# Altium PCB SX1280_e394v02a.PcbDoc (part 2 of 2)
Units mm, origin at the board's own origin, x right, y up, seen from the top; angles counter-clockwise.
Board outline 104.5 x 58 mm, 4 copper layers (Top Layer, MidLayer1, MidLayer2, Bottom Layer), stack 0.995 mm thick; 155 components, 106 nets, 471 pads, 1470 vias.
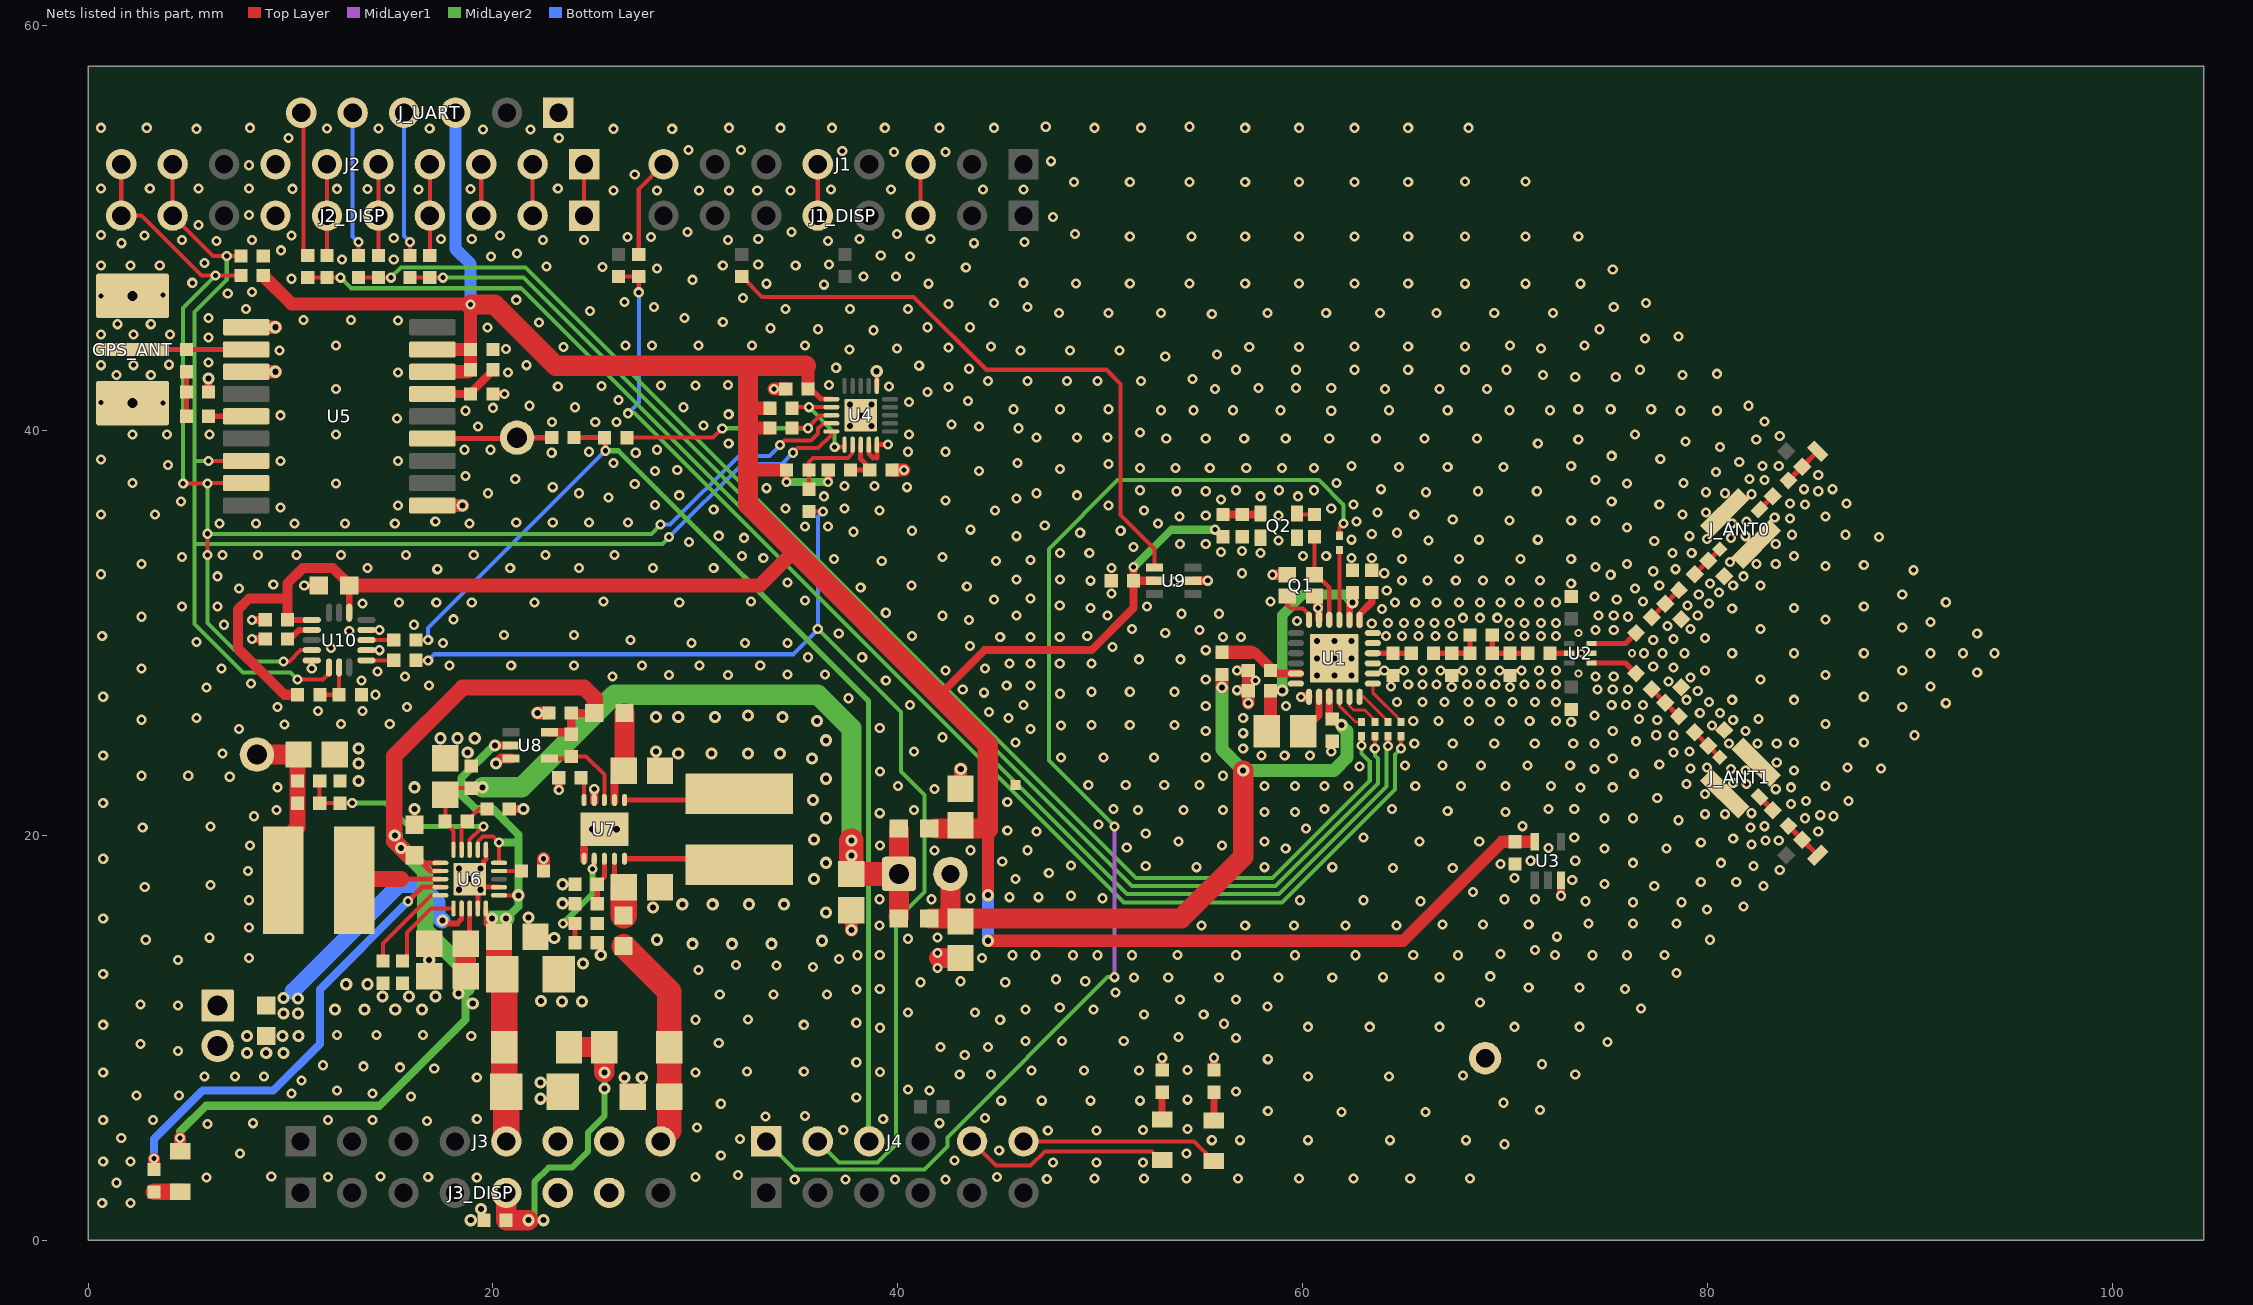
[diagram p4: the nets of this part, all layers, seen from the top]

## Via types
v1: diameter 0.5, hole 0.25, Top Layer to Bottom Layer, tented both sides, 1338 vias
v2: diameter 0.6, hole 0.3, Top Layer to Bottom Layer, tented both sides, 107 vias
v3: diameter 0.5, hole 0.3, Top Layer to Bottom Layer, tented top, 10 vias
v4: diameter 0.6, hole 0.3, Top Layer to Bottom Layer, tented top, 9 vias
v5: diameter 0.4, hole 0.2, Top Layer to Bottom Layer, tented both sides, 4 vias
v6: diameter 0.66, hole 0.33, Top Layer to Bottom Layer, tented top, 2 vias

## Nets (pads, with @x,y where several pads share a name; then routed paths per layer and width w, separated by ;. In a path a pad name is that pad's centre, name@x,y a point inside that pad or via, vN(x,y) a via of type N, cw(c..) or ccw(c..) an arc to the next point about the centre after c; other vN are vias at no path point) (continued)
GND: BAT1.2 C0.2 C1.1 C2.1 C5.1 C6.1 C7.1 C8.1 C9.1 C10.1 C11.1 C12.1 C13.1 C16.2 C17.2 C20.2 C21.1 C22.1 C23.1 C24.2 C25.2 C26.1 C27.1 C28.1 C29.1 C30.1 C31.2 C33.1 C34.1 C35.1 C36.1 C37.1 C38.1 C39.1 C40.1 C41.1 C42.2 C43.1 C44.1 C45.1 C46.1 C48.2 GND.1 GPS_ANT.2 J2.7 J2_DISP.7 J3.6 J3.7 J3_DISP.6 J3_DISP.7 J_ANT0.3 J_ANT0.4 J_ANT1.3 J_ANT1.4 J_UART.1 L5.1 L6.1 Q1.2 Q1.4 Q2.1 Q2.2 R14.1 R17.1 R18.1 R24.2 R25.2 R27.2 R29.2 R31.2 R32.2 R34.1 R37.1 R45.2 Shield.1 U1.5 U1.13 U1.20 U1.21 U1.23 U1.24 U1.25 U2.2 U3.3 U4.6 U4.19 U4.20 U4.21 U5.1 U5.10 U5.12 U6.2 U6.6 U6.19 U6.21 U7.4 U7.6 U7.11 U8.3 U9.2 U10.5 U10.10 U10.12 | length 33.6
  Top Layer w0.25: v2(5.95,42.575) v2@5.957,42.568 ; C29.1@16.125,20.525 v2(16.125,21.3) ; U6.19@19.25,16.394 U6.21@19.25,17.444 ; U6.6@19.65,19.294 19.65,18.829 19.537,18.716 19.537,18.532 v3(19.375,18.369) v3(18.85,17.844) U6.21@19.25,17.444 ; U6.2@20.3,17.444 U6.21@19.25,17.444 ; U4.19@38.561,39.3 38.561,38.861 38.772,38.65 ; v2(38.95,42.925) 38.95,42.875 38.961,42.864 U4.6@38.961,42.2 ; 38.961,38.65 U4.20@38.961,39.3 v1(39.5,39.3)
  Top Layer w0.3: v1(11.05,28.25) U10.5@11.05,28.65 ; U10.10@13.75,29.15 v1(14.4,29.15) ; U10.12@13.75,30.15 v1(14.4,30.15)
  Top Layer w0.4: C42.2@5.957,41.95 v2@5.957,42.568 ; v1(8.1,29.7) C44.1@8.75,29.7 ; v1@8.1,30.664 8.114,30.65 C43.1@8.75,30.65 ; v1@10.679,32.35 C45.1@11.4,32.35 ; C24.2@19.995,41.8 v1(20.575,41.8) ; R27.2@20.8,21.3 v2(21.5,21.3) ; v1(23.25,22.25) R32.2@23.25,22.85 ; U7.6@24.5,18.794 U7.6@24.5,18.85 24.5,19.35 ; U7.4@25,21.65 U7.4@25,21.75 v1(25,22.284) ; R17.1@53.05,8.421 v1(53.05,9.021) ; U9.2@54.569,32.58 v1(55.3,32.581) ; R18.1@55.6,8.421 v1(55.6,9.021) ; Q1.2@60.575,31.825 Q1.2@60.75,31.65 ; v1(60.75,31.228) 60.8,31.178 U1.5@60.8,30.65 ; v1@72.75,17.022 U3.3@72.75,17.789
  Top Layer w0.5: v2(20.15,23.55) 20.396,23.796 U8.3@20.892,23.796 ; v1(56.75,28.15) C8.1@57.3,28.15 ; v1@56.774,27.174 57.276,27.174 C9.1@57.3,27.15 ; v1(58.5,32.875) Q1.4@59.225,32.875 ; v1(59.896,26.83) 60.205,26.83 U1.13@60.225,26.85 ; v1(60.75,31.228) Q1.2@60.75,31.65
  Top Layer w0.6: v1(57.3,26.532) C9.1@57.3,27.15 C8.1@57.3,28.15
  Top Layer w0.65: U5.12@7.81,42.9 v2(9.25,42.9) ; U5.10@7.81,45.1 v2(9.25,45.1) ; U5.1@17.01,36.3 v2(18.5,36.3) ; v2(22.2,26.05) C30.1@22.767,26.05 ; R25.2@22.5,18.244 v1(22.5,18.85) ; v1(33.875,42.05) C20.2@34.461,42.05 ; v2(37.7,15.325) C40.1@37.7,16.3 ; R14.1@39.711,38.05 v1(40.3,38.05) ; C13.1@43.09,22.3 43.09,23.265 v2(43.1,23.275)
  Top Layer w1: 42.04,13.95 C7.1@43.09,13.95
  other v1: 0.7,1.85 2.1,1.85 1.4,2.85 34.9,3 37.4,3 39.85,3 42.35,3 47.35,3.037 49.7,3.05 52.15,3.05 54.25,3.05 56.8,3.05 59.8,3.05 62.5,3.05 65.3,3.05 68.25,3.05 5.85,3.1 19.2,3.1 11.85,3.13 16.8,3.13 30,3.13 44.9,3.13 14.45,3.15 9.05,3.166 32.1,3.237 47.65,3.85 49.8,3.85 52.1,3.85 0.75,3.9 2.1,3.9 42.8,3.95 31.25,4.2 7.5,4.3 54.25,4.3 45,4.45 69.95,4.75 55.5,4.95 56.886,4.95 60.25,4.95 64.3,4.95 68.05,4.95 32.2,5 1.64,5.05 47.4,5.435 49.8,5.435 37.3,5.45 52.1,5.45 54.3,5.5 30.067,5.578 5.9,5.75 8.15,5.79 42.05,5.79 16.75,5.9 0.75,5.95 3.2,5.95 11.85,5.95 14.05,5.95 19.2,6 39.271,6 44.3,6.05 33.45,6.125 35.4,6.15 61.9,6.35 66.05,6.35 58.264,6.4 71.7,6.45 31.25,6.75 69.9,6.8 45.1,6.9 47.1,6.9 49.5,6.9 51.95,6.9 54.3,6.95 37.943,7.05 15.95,7.1 2.4,7.15 4.5,7.15 10.05,7.25 14.05,7.25 56.7,7.35 12.3,7.4 41.55,7.4 40.49,7.45 10.55,7.9 19.2,8.05 5.75,8.1 7.25,8.1 8.7,8.1 60.25,8.1 64.25,8.1 67.9,8.15 43.05,8.2 44.6,8.2 73.45,8.2 0.75,8.3 30,8.3 39.11,8.321 32.55,8.35 35.35,8.35 46.6,8.4 49.192,8.4 51.9,8.4 54.3,8.421 17.1,8.5 15.4,8.55 13.6,8.6 11.6,8.65 71.8,8.7 37.943,8.8 58.264,8.95 43.3,9.15 4.45,9.35 42.1,9.55 44.44,9.55 2.6,9.7 31.15,9.75 75.05,9.8 46.3,9.85 48.1,9.85 51.15,9.85 56.7,10 53.85,10.05 18.925,10.1 12.3,10.15 14.25,10.15 16.55,10.15 39.11,10.504 60.25,10.55 63.3,10.55 66.75,10.55 70.45,10.55 73.65,10.55 0.75,10.65 35.35,10.65 56.1,10.7 37.943,10.75 30,10.9 45.05,10.9 32.6,10.906 52.15,11.15 55.1,11.15 40.49,11.25 43.8,11.264 46.3,11.4 49.65,11.4 76.7,11.45 47.991,11.5 58.249,11.55 4.45,11.6 2.6,11.65 68.75,11.75 53.931,11.9 56.7,11.9 31.2,12.15 33.85,12.15 36.5,12.15 50.75,12.25 37.95,12.4 39.1,12.425 75.9,12.425 71.15,12.5 73.65,12.5 41.12,12.75 45.299,12.75 43.081,12.8 49.25,12.8 47.8,12.9 51.65,12.977 53.35,12.977 55.85,12.977 58.8,12.977 61.45,12.977 63.95,13 66.75,13 69.25,13.044 0.75,13.15 78.45,13.2 30.15,13.35 41.947,13.45 35.8,13.5 34,13.585 32,13.6 4.45,13.85 37.083,13.9 7.95,13.95 44.159,13.95 37.998,14.085 39.1,14.1 45.65,14.085 46.8,14.085 48.65,14.085 49.85,14.085 51.564,14.085 53.8,14.1 56.7,14.085 59.6,14.085 62.6,14.085 65.45,14.1 67.65,14.085 72.45,14.1 74.3,14.085 76,14.085 77.85,14.1 69.75,14.15 41.947,14.2 71.462,14.35 2.85,14.85 80.1,14.85 40.49,14.9 6,14.95 41.947,14.967 72.55,15 7.95,15.45 39.084,15.55 55,15.55 57.15,15.55 59.55,15.55 62.1,15.55 64.616,15.55 66.9,15.6 68.9,15.6 71.15,15.6 74.1,15.65 76.3,15.65 78.45,15.65 0.75,15.9 79.95,16.35 81.75,16.5 76.3,16.7 78.7,16.7 65.8,16.75 73.95,16.75 7.95,16.8 59.85,16.8 63,16.8 39.084,16.85 41.65,16.85 69.95,16.85 71.462,16.85 43.587,16.9 50.1,16.9 45.5,16.95 46.95,16.95 48.55,17.022 72.751,17.022 68.4,17.2 2.8,17.45 77.35,17.5 82.75,17.5 6.05,17.55 74.9,17.6 79.65,17.7 81.4,17.7 73.3,17.8 45.8,17.85 70.45,17.9 47.45,18.15 7.9,18.25 83.55,18.3 64.45,18.4 67.4,18.4 54.75,18.433 58.1,18.433 61.45,18.433 48.55,18.523 52.239,18.5 82.25,18.5 69.766,18.592 76.3,18.65 80.65,18.65 45.15,18.709 71.25,18.75 73.45,18.75 0.75,18.85 41.8,19.25 43.587,19.268 46.4,19.268 59.15,19.35 74.9,19.35 77.95,19.35 72.124,19.386 51.3,19.4 8,19.5 39.11,19.5 56,19.5 82.15,19.55 79.65,19.65 53.85,19.7 58.1,19.7 65.75,19.7 68.707,19.7 82.85,19.75 83.5,19.75 81.25,19.85 63,19.9 73.4,19.9 52.239,20.1 46.85,20.2 85.45,20.2 45.4,20.25 60.149,20.35 2.7,20.4 82.1,20.4 6.05,20.45 70.85,20.457 82.8,20.457 49.9,20.55 78.55,20.75 74.9,20.85 76.3,20.85 84.8,20.85 8.2,20.95 86.2,20.95 85.55,21 79.85,21.05 80.85,21.05 39.1,21.1 82.15,21.1 58.1,21.15 59.6,21.15 70,21.15 67.15,21.2 9.3,21.25 40.8,21.25 51.85,21.25 54.1,21.25 56.05,21.25 50.65,21.3 61.057,21.3 64.4,21.3 72.124,21.3 73.4,21.3 84.1,21.55 0.75,21.6 45.4,21.65 84.85,21.7 86.95,21.7 77.5,21.85 79.85,22.05 41.8,22.3 83.35,22.284 9.35,22.378 73.7,22.36 75.3,22.378 84.1,22.378 40,22.45 58.1,22.45 59.6,22.45 61.057,22.45 62.25,22.45 65.55,22.45 67.8,22.45 70,22.45 72.25,22.45 85.8,22.45 49.4,22.5 51.25,22.5 53.15,22.5 54.9,22.5 78.95,22.55 81.9,22.55 81.25,22.6 7,22.9 2.65,22.95 4.95,22.95 56.05,22.95 76.35,23.05 39.11,23.15 81.85,23.2 84.25,23.2 74.4,23.275 81.15,23.275 79.15,23.3 88.55,23.3 79.95,23.35 86.9,23.35 62.8,23.4 65.05,23.45 66.9,23.45 68.8,23.45 71.1,23.45 73.2,23.45 77.6,23.5 83.4,23.6 75.3,23.8 48.05,23.85 50.15,23.85 52.65,23.85 55.2,23.85 0.75,23.95 57.95,23.95 59.1,23.95 60.35,23.95 6.65,24.05 78.3,24.1 40.8,24.15 61.4,24.15 79.1,24.15 57.05,24.3 65.5,24.55 67.4,24.55 69.45,24.55 71.45,24.55 73.35,24.55 74.4,24.55 81.05,24.55 82.45,24.55 83.4,24.55 45.8,24.6 84.25,24.6 87.7,24.6 76.45,24.65 42.2,24.85 77.45,24.95 78.3,24.95 90.2,24.95 57.05,25.05 55.2,25.15 75.3,25.15 81.85,25.15 7.45,25.25 46.55,25.25 39.1,25.3 48.05,25.425 80.2,25.425 49.55,25.45 51.45,25.45 53.65,25.45 9.7,25.487 12.5,25.5 14.9,25.5 85.8,25.5 73.25,25.6 65.45,25.65 66.7,25.65 68.2,25.65 69.7,25.65 71.2,25.65 72.5,25.65 77.5,25.7 81.25,25.7 2.65,25.716 76.6,25.75 82.5,25.75 5.35,25.8 45.454,25.8 57.05,25.8 74.4,25.917 79.6,26.05 80.6,26.05 44.5,26.1 11.35,26.156 13.55,26.15 9.35,26.35 15.75,26.35 89.6,26.35 55.2,26.4 59.168,26.4 40.6,26.44 75.25,26.44 46.2,26.45 75.95,26.45 76.8,26.45 91.75,26.532 64.65,26.583 65.9,26.583 67,26.583 68.17,26.583 69.25,26.583 70.35,26.583 71.462,26.583 72.5,26.583 80.05,26.6 78.95,26.7 81.2,26.7 84.25,26.7 37.55,26.775 0.75,26.85 87.7,26.85 14.2,26.95 48,27 44.25,27.05 49.55,27.097 51.45,27.097 53.65,27.097 79.5,27.134 56.75,27.174 43.2,27.2 74.55,27.2 75.3,27.2 76.05,27.2 5.85,27.3 67.35,27.325 70.228,27.325 64.35,27.35 91,27.35 16.832,27.4 45.37,27.4 46.55,27.4 65.2,27.45 65.9,27.45 66.6,27.45 68.1,27.45 68.8,27.45 69.5,27.45 70.95,27.45 71.75,27.45 72.5,27.45 8.05,27.5 78.05,27.6 13.5,27.65 39.4,27.659 57.65,27.65 55.2,27.7 82.6,27.7 79.15,27.8 15.65,27.85 25.9,27.85 74.45,27.85 75.35,27.85 28.7,27.925 31.6,27.925 85.8,27.925 34.55,27.95 36.4,27.95 93.3,28.05 14.3,28.1 42.35,28.15 64.017,28.15 65,28.15 65.9,28.15 66.8,28.15 67.9,28.15 68.8,28.15 69.7,28.15 70.8,28.15 71.65,28.15 72.5,28.15 79.85,28.15 89.6,28.15 2.65,28.25 44.3,28.25 6.6,28.253 78.3,28.3 77.3,28.35 17.85,28.4 20.9,28.4 24,28.4 27.35,28.4 30.2,28.4 33.2,28.4 45.5,28.5 46.55,28.5 47.991,28.5 49.557,28.5 51.9,28.7 53.95,28.7 35.55,28.8 38.234,28.8 76.85,29 77.75,29 78.85,29 81.2,29 84.25,29 87.7,29 91,29 92.6,29 94.15,29 55.2,29.15 12,29.25 50.59,29.3 43.55,29.35 17.533,29.5 29.8,29.5 32.45,29.5 34.55,29.5 5.35,29.55 26.8,29.65 77.3,29.65 78.3,29.7 79.85,29.75 45.05,29.8 46.55,29.8 47.991,29.8 56.05,29.8 56.95,29.8 0.7,29.85 40.7,29.85 49.35,29.85 64.1,29.85 64.9,29.85 65.7,29.85 66.55,29.85 67.4,29.85 70.2,29.85 70.95,29.85 71.75,29.85 72.5,29.85 20.55,29.9 24,29.9 37.077,29.975 93.3,29.975 53.2,30 12.9,30.1 54.9,30.15 74.45,30.15 75.35,30.15 51.55,30.2 79.15,30.2 82.6,30.2 89.6,30.275 78,30.35 6.72,30.407 16.1,30.407 63.4,30.469 64.2,30.5 65,30.5 65.75,30.5 66.5,30.5 67.25,30.5 70.2,30.5 70.95,30.5 71.75,30.5 72.5,30.5 91,30.55 59.7,30.6 8.1,30.65 43.5,30.65 85.8,30.664 18.05,30.676 67.9,30.75 68.75,30.75 69.6,30.75 2.65,30.8 76.05,30.8 42.2,30.85 45.85,30.866 50.35,30.86 74.6,30.86 75.35,30.866 79.5,30.866 54,30.95 55.85,30.95 39.4,31 63.9,31.178 81.2,31.2 49.5,31.228 84.25,31.228 4.65,31.3 6.4,31.3 52.3,31.303 87.7,31.3 47.991,31.35 79,31.35 13.55,31.45 80.05,31.45 15.35,31.5 17.2,31.5 18.95,31.5 22.05,31.5 29.2,31.5 64.55,31.5 65.55,31.5 66.6,31.5 67.7,31.5 68.75,31.5 69.75,31.5 70.7,31.5 71.65,31.5 72.5,31.518 91.75,31.518 25.45,31.55 32.75,31.55 58.4,31.55 76.8,31.55 35.4,31.6 44.75,31.65 75.5,31.65 46.55,31.7 74.4,31.8 79.55,31.9 89.6,31.9 50.55,31.95 80.55,32 64.139,32.1 7.45,32.2 76.4,32.2 38.161,32.25 43.4,32.3 10.679,32.35 40.671,32.35 77.6,32.35 81.25,32.35 82.6,32.35 9.15,32.4 73.25,32.45 80.1,32.45 34.55,32.5 53.65,32.55 49.5,32.581 64.9,32.6 66.15,32.6 67.55,32.6 68.9,32.6 70.228,32.6 71.7,32.6 45.85,32.65 48,32.65 6.4,32.8 81.75,32.8 75.2,32.875 0.65,32.9 57,32.95 64.017,32.95 77.3,33.05 90.15,33.1 17.25,33.15 78.4,33.15 13.8,33.2 20.85,33.2 24.25,33.2 27.9,33.2 30.9,33.2 50.55,33.2 74.45,33.25 85.8,33.3 87.7,33.362 2.65,33.4 76,33.4 82.4,33.4 83.35,33.4 81.1,33.5 39.2,33.55 44.85,33.55 46.55,33.6 36.85,33.65 64.9,33.65 67.7,33.65 70.75,33.65 73.25,33.65 33.35,33.7 62.4,33.7 63.4,33.7 4.65,33.75 42.2,33.75 32.3,33.8 60,33.8 61.15,33.8 84.25,33.8 6.65,33.85 8.4,33.85 10.3,33.85 12.5,33.85 15.7,33.85 19.05,33.85 22.6,33.85 26,33.85 48,33.95 49.45,33.95 57.9,33.95 78.25,33.95 79.2,33.95 55.95,34 57,34.05 51.634,34.25 53.931,34.4 55.2,34.4 83.35,34.4 29.685,34.5 77.35,34.55 58.8,34.568 66.2,34.568 62.4,34.606 68.7,34.606 71.6,34.606 79.95,34.65 32.404,34.7 81.15,34.7 88.45,34.738 31.15,34.8 45.85,34.78 79.1,34.78 81.85,34.78 84.15,34.85 86.8,34.85 63.399,34.892 49,34.95 64.637,34.95 37.8,35 40.7,35.05 51,35.05 43.587,35.1 76,35.2 35.4,35.256 36.55,35.256 47.25,35.3 6.5,35.4 8.3,35.4 10.2,35.4 12.7,35.4 15.15,35.4 18.842,35.4 52.85,35.4 81.2,35.4 21.15,35.45 22.95,35.45 24.75,35.45 26.66,35.45 17.15,35.5 62.65,35.5 81.9,35.5 70.202,35.56 73.25,35.56 74.45,35.56 67.4,35.6 84.05,35.65 83.3,35.7 53.9,35.75 85.8,35.75 55.2,35.8 58.8,35.8 0.65,35.85 3.3,35.85 65.5,35.85 78.75,35.85 63.681,35.95 79.9,35.95 39.084,36.05 44.8,36.05 52.15,36.05 30.9,36.1 34.45,36.15 37.361,36.15 61.4,36.15 9.5,36.2 15.3,36.3 50.4,36.3 28,36.325 62.5,36.35 77.6,36.35 84.8,36.35 84.05,36.4 86.85,36.4 4.6,36.5 75.25,36.5 42.35,36.55 55.95,36.6 45.85,36.65 25.703,36.7 36.35,36.75 57.9,36.75 59.75,36.75 29.2,36.8 48.85,36.8 82.15,36.85 19.75,36.9 24.25,36.9 46.85,36.9 80.85,36.9 66.075,36.95 79.9,36.95 53.75,37 55.2,37 68.65,37 71.55,37 85.45,37 51.95,37.05 56.7,37.05 58.809,37.05 60.55,37.05 63.85,37.1 84.75,37.1 86.15,37.1 33.5,37.15 22.95,37.2 40.45,37.2 37.361,37.25 38.85,37.25 27,37.35 12.25,37.375 76,37.375 2.2,37.4 61.65,37.4 78.8,37.4 74.45,37.55 82.8,37.55 21.1,37.602 82.05,37.602 18.65,37.75 85.45,37.8 80.4,37.95 28,38 44,38 29.1,38.05 48,38.1 51.95,38.15 53.7,38.15 55.4,38.15 57.2,38.15 58.97,38.15 60.55,38.15 64.75,38.2 67.15,38.2 69.9,38.2 62.4,38.25 73.25,38.25 82.7,38.25 83.5,38.25 3.95,38.3 50.4,38.35 25.95,38.4 45.9,38.4 81.55,38.45 9.5,38.5 15.3,38.5 0.65,38.56 77.65,38.6 75.25,38.75 22.9,38.9 27.05,38.9 24.75,38.95 40.49,38.95 42.35,38.95 18.6,39.05 19.875,39.05 28.1,39.05 80.6,39.177 31.641,39.35 71.6,39.35 78.9,39.45 73.6,39.55 82.39,39.55 53.25,39.6 55.2,39.6 57.1,39.6 59.15,39.6 61.3,39.6 63.6,39.6 66,39.6 68.6,39.6 46.85,39.65 48.85,39.65 50.35,39.65 83.55,39.725 2.2,39.8 3.9,39.8 6,39.8 12.25,39.8 40.55,39.8 76.4,39.8 51.95,39.9 45.95,40.112 19.264,40.2 44,40.2 30.4,40.25 42.65,40.3 22.91,40.412 25.05,40.412 26.1,40.412 82.8,40.45 15.25,40.6 9.5,40.75 31.641,40.8 18.65,40.975 61.4,40.975 78.65,40.975 80.45,40.975 53,41 54.6,41 56.55,41 58.9,41 64.25,41 67.15,41 70.2,41 72.2,41 45.7,41.05 48,41.05 50.4,41.05 73.6,41.05 75.2,41.05 77.2,41.05 20,41.122 24.05,41.147 29.4,41.147 21.805,41.223 82,41.223 3.7,41.35 0.65,41.376 40.55,41.4 43.45,41.45 26.2,41.5 41.45,41.9 12.25,42.05 55.65,42.05 64.05,42.05 66.75,42.05 69.1,42.05 57.8,42.1 59.65,42.1 61.4,42.1 42.5,42.15 23.2,42.18 39.55,42.18 25.35,42.2 28.3,42.231 30,42.231 31.6,42.25 36.6,42.25 44.45,42.45 46.4,42.45 48.35,42.45 49.85,42.45 52,42.45 54.55,42.55 73.45,42.65 75.45,42.65 1.4,42.75 3.1,42.75 71.85,42.75 78.75,42.75 80.45,42.8 15.3,42.873 20.75,42.864 56.7,43 59.65,43 62.55,43 65.2,43 68,43 70.05,43 76.65,43 43.5,43.05 36.95,43.1 41.05,43.2 0.65,43.225 2.25,43.225 21.65,43.225 4,43.25 5.957,43.35 53.2,43.65 55.75,43.75 9.45,43.95 46.05,43.95 48.5,43.95 50.95,43.95 20.65,44.017 37.6,44 39.95,44.05 71.75,44.05 42.5,44.1 23.476,44.119 57.35,44.119 59.802,44.119 44.6,44.15 62.55,44.15 65.2,44.15 68,44.15 12.25,44.2 26.55,44.2 27.85,44.2 30.15,44.2 32.8,44.2 35.4,44.2 70.228,44.2 73.9,44.2 76.9,44.55 5.95,44.6 78.55,44.65 0.65,44.75 2.25,44.75 4.05,44.75 38.8,44.95 36.05,45 74.65,45 33.7,45.05 19.728,45.084 41.45,45.1 43.55,45.1 1.45,45.25 3.1,45.25 22.268,45.338 31.35,45.35 15.3,45.44 10.65,45.45 12.981,45.45 5.95,45.55 29.45,45.55 55.5,45.75 47.95,45.8 50.4,45.8 53,45.8 58.249,45.8 61.15,45.8 63.8,45.8 66.6,45.8 69.45,45.8 72.35,45.8 24.8,45.9 7.8,46 34.45,46 37.636,46 40.5,46 27.95,46.1 46.4,46.1 75.35,46.1 42.5,46.25 44.75,46.3 76.95,46.3 26.5,46.35 21.15,46.455 32.35,46.55 0.65,46.65 3.7,46.7 6.9,46.758 8.1,46.848 36.345,47.2 33.5,47.25 41.5,47.25 68,47.25 71,47.25 73.7,47.25 48.8,47.256 51.45,47.256 54.4,47.256 57.15,47.256 59.8,47.256 62.55,47.256 65.2,47.256 5.15,47.295 46.2,47.295 29.85,47.443 10.044,47.494 38.3,47.6 39.9,47.6 75.3,47.95 28.1,48 43.35,48.046 25.4,48.075 22.65,48.1 0.65,48.15 2.09,48.15 3.543,48.15 31.35,48.15 34.95,48.15 33.1,48.2 36.6,48.2 5.75,48.278 12.55,48.45 15.1,48.45 19.9,48.6 40.6,48.6 39.15,48.65 21.19,48.75 9.524,48.9 1.65,49.25 43.75,49.25 46.25,49.3 6.352,49.35 36.55,49.353 4.65,49.4 8.1,49.4 22.477,49.4 24.5,49.4 31.6,49.4 17.43,49.45 18.95,49.45 33.1,49.45 38.1,49.45 41.6,49.45 15.1,49.5 26.65,49.55 27.8,49.55 51.45,49.581 54.5,49.581 57.15,49.581 59.8,49.581 62.55,49.581 65.2,49.581 68,49.581 71,49.581 73.6,49.581 2.791,49.63 10.05,49.63 20.35,49.63 0.65,49.65 39.95,49.7 48.75,49.7 29.6,49.8 34.75,49.8 5.45,50.15 47.65,50.55 7.95,50.65 33.05,51.846 25.95,51.85 28.1,51.85 30.18,51.85 31.65,51.85 34.7,51.85 16.33,51.9 36.7,51.9 39.65,51.9 44.2,51.9 46.2,51.9 10.1,51.936 12.3,51.936 13.8,51.93 14.9,51.93 18.888,51.93 0.65,51.95 3.05,51.95 5.45,51.95 7.95,51.95 23.2,51.95 48.7,52.281 51.45,52.281 54.4,52.281 57.15,52.281 59.8,52.281 62.55,52.281 65.2,52.281 68,52.3 71,52.3 27,52.65 7.95,53.1 47.55,53.3 39.8,53.75 42.35,53.75 37.25,53.8 29.65,53.85 32.25,53.85 9.9,54.45 23.25,54.45 19.501,54.874 21.85,54.874 5.35,54.9 11.8,54.91 14.34,54.91 16.875,54.91 25.95,54.9 28.85,54.9 0.65,54.95 2.9,54.95 8,54.95 31.65,54.95 34.2,54.95 36.75,54.95 39.35,54.95 42.05,54.95 44.75,54.95 49.7,54.95 52,54.95 57.15,54.95 59.802,54.95 62.55,54.95 65.2,54.95 68.17,54.95 47.3,55 54.4,55
  other v2: 18.9,1 19.4,1.55 22.35,7 22.35,7.8 26.5,8.05 27.35,8.05 7.85,9.25 8.8,9.25 9.65,9.25 7.85,10.1 9.6,10.1 10.4,10.1 12.192,11.4 13.65,11.4 15.173,11.4 16.494,11.4 23.4,11.8 24.4,11.8 22.375,11.825 14.55,12.05 15.85,12.05 17.152,12.05 12.75,12.65 13.8,12.65 24.45,13.675 16.85,13.85 25.325,14.1 29.85,14.65 31.8,14.65 33.75,14.65 36.25,14.8 28.1,14.85 23.025,14.938 21.75,15.95 36.45,16.2 27.9,16.45 29.35,16.6 30.85,16.6 32.65,16.6 34.375,16.6 23.425,16.65 23.425,17.589 35.85,17.844 36.45,18.65 35.85,19.8 36.45,20.85 35.8,21.75 16.125,22.378 13.35,22.694 36.45,22.8 13.35,23.55 35.75,23.8 29.15,24.05 30.8,24.05 32.6,24.05 34.175,24.05 18.75,24.1 28.05,24.15 13.35,24.3 36.45,24.7 17.4,24.8 18.25,24.8 19.1,24.8 36,25.65 28.05,25.85 29.15,25.85 30.96,25.85 34.3,25.85 32.6,25.917
  other v3: 18.325,17.319 19.375,17.319 18.325,18.369 37.636,40.225 38.686,40.225 38.161,40.75 37.636,41.275 38.686,41.275
  other v4: 60.7,27.9 61.55,27.9 62.4,27.9 60.7,28.75 61.55,28.75 62.4,28.75 60.7,29.6 61.55,29.6 62.4,29.6
  other v5: 73.6,28 73.75,29 76.25,29 73.6,30
  other v6: 24.9,20.3 26.1,20.3
LED_RX: J4.6 RX.1 | length 9.8
  Top Layer w0.2: J4.6@46.2,4.89 54.631,4.89 RX.1@55.6,3.921
LED_TX: J4.5 TX.1 | length 10.4
  Top Layer w0.2: J4.5@43.66,4.89 44.85,3.7 46.556,3.7 47.256,4.4 52.55,4.4 52.979,3.971 TX.1@53.05,3.971
MISO: J2.5 J2_DISP.5 R50.1 | length 4.5
  Top Layer w0.2: R50.1@14.34,48.65 J2_DISP.5@14.34,50.61 J2.5@14.34,53.15
MISO_TX: R9.1 R42.2 R50.2 | length 67
  Top Layer w0.2: R42.2@13.35,47.55 14.336,47.55 R50.2@14.34,47.546 ; R50.2@14.34,47.55 v1@14.955,47.55 ; v1@14.953,47.548 v1(14.955,47.546) ; v1(62.9,24.448) R9.1@62.9,24.9
  MidLayer2 w0.2: v1@14.95,47.546 15.45,48.046 21.604,48.046 51.75,17.9 58.5,17.9 63.3,22.7 63.3,23.646 62.9,24.046 v1(62.9,24.448) v1(62.9,24.448)
MOSI: J2.4 J2_DISP.4 R49.1 | length 4.5
  Top Layer w0.2: R49.1@16.88,48.65 J2_DISP.4@16.88,50.61 J2.4@16.88,53.15
MOSI_RX: R4.2 R8.1 R49.2 | length 64.8
  Top Layer w0.2: R4.2@15.9,47.546 15.904,47.55 R49.2@16.88,47.55 16.884,47.546 v1(17.533,47.546) ; v1(63.55,24.3) R8.1@63.55,24.9
  MidLayer2 w0.2: v1(17.533,47.546) 21.504,47.546 51.55,17.5 58.65,17.5 63.71,22.56 63.71,23.79 63.55,23.95 v1(63.55,24.3)
NetANT0_1: ANT0.1 C19.1 L10.2 | length 2.1
  Top Layer w0.25: C19.1@83.981,37.531 C19.1@83.981,37.531 L10.2@84.652,38.202 ; L10.2@84.652,38.202 85.43,38.98 ANT0.1@85.43,38.99
NetANT1_1: ANT1.1 C18.1 L9.2 | length 2.1
  Top Layer w0.25: C18.1@83.981,20.469 84.65,19.8 L9.2@84.66,19.8 ; L9.2@84.652,19.797 ANT1.1@85.43,19.02
NetBAT1_1: BAT1.1 C39.2 U6.17 | length 12.6
  Top Layer w0.25: 18.237,15.662 18.45,15.875 U6.17@18.45,16.394 U6.17@18.45,16.675
  Top Layer w0.3: v2(17.5,15.8) 17.638,15.662 18.237,15.662
  Bottom Layer w0.8: 10.105,12.305 15.35,17.55 16.4,17.55 17.25,16.7 17.25,16.05 v2(17.5,15.8)
  other v2: 9.65,11.2 10.373,11.2 10.373,11.95 9.65,11.975
NetC0_1: C0.1 L1.1 U1.22 | length 1.9
  Top Layer w0.25: U1.22@63.45,29 C0.1@64.45,29 L1.1@65.35,29
NetC1_2: C1.2 C4.1 L1.2 L2.1 | length 2.7
  Top Layer w0.25: L1.2@66.45,29 C1.2@67.35,29 L2.1@68.25,29 C4.1@68.25,29.9
NetC2_2: C2.2 C3.1 C4.2 L2.2 | length 2.7
  Top Layer w0.25: C4.2@69.35,29.9 L2.2@69.35,29 C2.2@70.228,29 C3.1@71.1,29
NetC3_2: C3.2 U2.5 | length 1
  Top Layer w0.25: C3.2@72.2,29 U2.5@73.15,29
NetC14_1: C14.1 L5.2 L7.1 | length 1.9
  Top Layer w0.25: C14.1@77.228,27.222 L5.2@77.899,26.55 L7.1@78.571,25.878 L7.1@78.571,25.878
NetC14_2: C14.2 U2.1 | length 2.4
  Top Layer w0.25: U2.1@74.25,28.52 75.93,28.52 C14.2@76.45,28
NetC15_1: C15.1 L6.2 L8.1 | length 1.9
  Top Layer w0.25: C15.1@77.228,30.778 L6.2@77.9,31.45 L8.1@78.571,32.121 L8.1@78.58,32.12
NetC15_2: C15.2 U2.3 | length 2.4
  Top Layer w0.25: U2.3@74.25,29.48 75.93,29.48 C15.2@76.45,30
NetC16_1: C16.1 J_ANT1.2 L7.2 | length 1.8
  Top Layer w0.25: L7.2@79.349,25.101 C16.1@80.021,24.429 ; C16.1@80.021,24.426 C16.1@80.021,24.429 ; J_ANT1.2@80.59,23.863 J_ANT1.2@80.586,23.863 C16.1@80.021,24.429
NetC17_1: C17.1 J_ANT0.2 L8.2 | length 1.7
  Top Layer w0.25: L8.2@79.349,32.899 C17.1@80.021,33.571 ; C17.1@80.021,33.571 J_ANT0.2@80.587,34.137
NetC18_2: C18.2 J_ANT1.1 | length 0.9
  Top Layer w0.25: J_ANT1.1@82.549,21.901 83.19,21.26 C18.2@83.203,21.26
NetC19_2: C19.2 J_ANT0.1 | length 0.9
  Top Layer w0.25: J_ANT0.1@82.549,36.099 83.2,36.75 C19.2@83.2,36.753
NetC24_1: C24.1 R20.2 U5.6 | length 3.5
  Top Layer w0.4: U5.6@17.01,41.8 C24.1@18.895,41.8 18.895,41.855 19.995,42.955 R20.2@19.995,43
NetC32_1: C32.1 R28.2 R29.1 U6.8 | length 11.1
  Top Layer w0.2: R28.2@11.442,22.694 C32.1@11.442,21.594 R29.1@12.442,21.594 13.044,21.594 v1(13.05,21.6) ; U6.8@18.85,19.294 18.85,19.788 19.356,20.294 19.451,20.294 v1@19.525,20.369 ; v1@19.478,20.416 v1@19.518,20.457
  MidLayer2 w0.25: v1(13.05,21.6) 14.673,21.6 15.823,20.45 v1(19.525,20.45)
NetC34_2: C34.2 R38.2 U7.2 | length 4.6
  Top Layer w0.4: U7.2@26,21.65 U7.2@26,21.75 26,22.75 C34.2@26.45,23.2 C34.2@26.5,23.25
  Top Layer w1: C34.2@26.5,23.25 R38.2@26.5,26.05
NetC35_2: C35.2 R35.2 R36.1 U7.9 | length 3
  Top Layer w0.25: U7.9@26,18.85 26,17.9 C35.2@26.45,17.45 ; R36.1@26.43,16.025 R36.1@26.45,16.044
  Top Layer w1.3: R36.1@26.45,16.044 C35.2@26.45,17.45
NetC36_2: C36.2 R37.2 U7.8 | length 2.4
  Top Layer w0.25: R37.2@25.15,16.625 C36.2@25.15,17.589 25.5,17.939 U7.8@25.5,18.85
NetC42_1: C42.1 L11.2 R19.2 | length 2.2
  Top Layer w0.257: R19.2@4.857,40.7 C42.1@4.857,41.9 L11.2@4.857,42.9
NetC44_2: C44.2 U10.2 | length 1.4
  Top Layer w0.3: C44.2@9.85,29.7 9.974,29.7 10.424,30.15 U10.2@11.05,30.15
NetC46_2: C46.2 FB1.2 Q2.4 | length 1.9
  Top Layer w0.2: Q2.4@57.85,35.85 Q2.4@57.9,35.9
  Top Layer w0.4: FB1.2@56.05,35.85 C46.2@57,35.85 Q2.4@57.85,35.85
NetC47_1: C47.1 Q2.3 | length 0.9
  Top Layer w0.2: Q2.3@59.7,35.9 59.75,35.85 C47.1@60.575,35.85
NetCHARGE_2: CHARGE.2 R30.2 | length 1.3
  Top Layer w0.8: R30.2@3.25,2.4 CHARGE.2@4.55,2.4
NetGPS_ANT_1: GPS_ANT.1 L11.1 U5.11 | length 5.6
  Top Layer w0.257: GPS_ANT.1@2.2,44 U5.11@7.81,44
NetL12_1: L12.1 U6.13 | length 4.3
  Top Layer w0.25: 15.45,17.844 U6.13@17.4,17.844
  Top Layer w0.8: L12.1@13.198,17.844 15.45,17.844
  Top Layer w1: L12.1@13.153,17.8 L12.1@13.198,17.844
NetL13_1: L13.1 U7.1 | length 5.8
  Top Layer w0.25: U7.1@26.5,21.75 31.847,21.75 L13.1@32.15,22.053
NetL13_2: L13.2 U7.10 | length 5.8
  Top Layer w0.25: U7.10@26.5,18.85 31.847,18.85 L13.2@32.15,18.547
NetQ1_1: Q1.1 U1.6 | length 2
  Top Layer w0.2: Q1.1@59.225,31.825 59.225,31.375 59.4,31.2 60,31.2 60.3,30.9 U1.6@60.3,30.65
NetR6_2: R6.2 U9.4 | length 30.9
  Top Layer w0.2: R6.2@32.286,47.6 33.286,46.6 40.778,46.6 44.378,43 50.3,43 51,42.3 51,35.819 52.669,34.151 U9.4@52.669,33.23 U9.4@52.88,33.23
NetR7_2: R7.2 U1.19 | length 2.5
  Top Layer w0.15: U1.19@63.45,27.5 63.45,27.05 64.85,25.65 R7.2@64.85,25.6
NetR8_2: R8.2 U1.17 | length 2.1
  Top Layer w0.15: U1.17@62.3,26.85 62.3,26.4 62.5,26.2 63.049,26.2 63.55,25.699 R8.2@63.55,25.6
NetR9_2: R9.2 U1.16 | length 1.9
  Top Layer w0.15: U1.16@61.8,26.85 61.8,26.4 62.601,25.599 R9.2@62.9,25.6
NetR10_2: R10.2 U1.18 | length 2
  Top Layer w0.15: U1.18@62.8,26.9 62.85,26.85 62.993,26.85 64.2,25.643 R10.2@64.2,25.6
NetR11_2: R11.2 U4.12 U4.16 | length 5.1
  Top Layer w0.2: R11.2@34.775,41.1 34.825,41.15 v1(35.6,41.15) U4.12@36.711,41.15 ; v1(36.877,39.177) 37.361,39.177 U4.16@37.361,39.3
  MidLayer2 w0.2: v1(35.6,41.15) 36.877,39.873 v1(36.877,39.177)
NetR13_1: R13.1 R14.2 U4.18 | length 2.4
  Top Layer w0.25: R13.1@37.661,38.05 R14.2@38.611,38.05 38.611,38.139 38.161,38.589 U4.18@38.161,39.3
NetR17_2: R17.2 TX.2 | length 1.4
  Top Layer w0.35: TX.2@53.05,5.971 R17.2@53.05,7.321
NetR18_2: R18.2 RX.2 | length 1.4
  Top Layer w0.35: RX.2@55.6,5.921 R18.2@55.6,7.321
NetR19_1: R19.1 U5.14 | length 1.9
  Top Layer w0.257: R19.1@5.957,40.7 U5.14@7.81,40.7
NetR21_1: R21.1 R40.2 U4.13 | length 11.5
  Top Layer w0.2: R40.2@26.477,39.65 30.873,39.65 v1(31.323,40.1) ; R21.1@34.775,40.125 35.537,40.125 36.162,40.75 U4.13@36.711,40.75
  MidLayer2 w0.2: v1(31.323,40.1) 31.335,40.112 v1(35.55,40.112)
NetR24_1: R24.1 U6.15 | length 4.7
  Top Layer w0.2: R24.1@14.575,13.8 14.575,14.675 16.944,17.044 U6.15@17.4,17.044
NetR25_1: R25.1 U6.4 | length 1.1
  Top Layer w0.2: U6.4@20.3,18.244 R25.1@21.4,18.244
NetR26_2: R26.2 R27.1 U6.9 | length 2.8
  Top Layer w0.2: U6.9@18.45,19.294 18.45,20.421 R26.2@18.73,20.7 18.73,20.73 19.3,21.3 R27.1@19.7,21.3
NetR30_1: R30.1 U6.14 | length 22.4
  Top Layer w0.25: v1(15.8,16.75) 16.494,17.444 U6.14@17.4,17.444
  Top Layer w0.6: R30.1@3.25,3.5 v1(3.25,4.05)
  Bottom Layer w0.4: v1(3.25,4.05) 3.25,5 5.65,7.4 9.15,7.4 11.45,9.7 11.45,12.4 v1(15.8,16.75)
NetR31_1: R31.1 U6.16 | length 4.3
  Top Layer w0.2: R31.1@15.531,13.8 15.75,14.019 15.75,15.2 16.944,16.394 U6.16@18.05,16.394
NetR32_1: R32.1 U7.5 | length 1.2
  Top Layer w0.2: R32.1@24.35,22.85 24.5,22.7 U7.5@24.5,21.75
NetR33_1: R33.1 U10.11 | length 1.4
  Top Layer w0.2: U10.11@13.75,29.65 R33.1@15.1,29.65
NetR34_2: R34.2 R35.1 U7.7 | length 5.4
  Top Layer w0.25: R34.2@24.05,14.7 R35.1@24.05,15.65 ; v1(24.909,18.341) 25,18.433 U7.7@25,18.85
  Top Layer w0.3: v1(23.45,15.65) R35.1@24.05,15.65
  MidLayer2 w0.3: v1(23.45,15.65) 24.909,17.109 v1(24.909,18.341)
NetR39_2: R39.2 U7.3 U8.4 | length 4.4
  Top Layer w0.2: U8.4@22.792,23.796 23.763,23.796 R39.2@23.867,23.9 24.6,23.9 25.5,23 U7.3@25.5,21.75
NetR44_2: R44.2 R45.1 U10.7 | length 2.3
  Top Layer w0.2: R44.2@11.442,26.95 R44.2@11.45,26.95 R45.1@12.4,26.95 U10.7@12.4,28.3
NetR46_1: R46.1 U10.9 | length 1.4
  Top Layer w0.2: U10.9@13.75,28.65 R46.1@15.1,28.65
NetR52_1: R52.1 U1.3 | length 3.4
  Top Layer w0.2: U1.3@61.8,30.65 R52.1@61.8,34.1
NIRQ1_PPS: J4.3 R33.2 R40.1 R41.2 | length 55.7
  Top Layer w0.2: R33.2@16.2,29.65 v1(16.8,29.65)
  Top Layer w0.257: R41.2@24,39.65 25.55,39.65 v1(25.55,39)
  MidLayer2 w0.257: v1(25.55,39) 26.187,39 38.551,26.636 J4.3@38.551,4.919
  Bottom Layer w0.2: v1(16.8,29.65) 16.8,30.25 v1(25.55,39)
  Bottom Layer w0.257: J4.3@38.551,4.919 J4.3@38.58,4.89
NIRQ2_NRST: J4.2 R46.2 R47.1 | length 60
  Top Layer w0.2: R46.2@16.2,28.65 v1(16.8,28.65) ; R47.1@35.6,36 v1@36.312,36
  MidLayer2 w0.2: J4.2@36.04,4.89 37.08,3.85 39,3.85 39.9,4.75 39.9,15.807 41.3,17.207 41.3,22 40.15,23.15 40.15,26.097 36.047,30.2 v1(36.04,30.2)
  Bottom Layer w0.2: v1(16.8,28.65) 17.1,28.95 34.839,28.95 v1@36.05,30.161 ; v1@36.05,30.2 36.05,35.75 v1(36.3,36)
NSS: J1.8 R48.1 | length 5
  Top Layer w0.2: R48.1@27.2,48.7 27.2,51.93 J1.8@28.42,53.15
NSS_CTS: R3.2 R7.1 R48.2 | length 60.9
  Top Layer w0.2: R3.2@26.2,47.6 R48.2@27.2,47.6 27.2,46.85 27.225,46.825 v1(27.2,46.825) ; v1(64.85,24.3) R7.1@64.85,24.9
  MidLayer2 w0.2: v1@26.75,40.875 26.982,40.875 51.157,16.7 58.97,16.7 64.55,22.28 64.55,24 v1(64.85,24.3)
  Bottom Layer w0.2: v1(26.66,40.85) 27.2,41.39 v1(27.2,46.825)
PPS: GPS_PPS.1 R41.1 U5.4 | length 5.9
  Top Layer w0.257: U5.4@17.01,39.6 21.145,39.6 GPS_PPS.1@21.19,39.645 R41.1@22.9,39.645
RTS: J_UART.6 R43.1 | length 7.2
  Top Layer w0.2: J_UART.6@10.53,55.69 10.65,55.57 10.65,48.85 R43.1@10.85,48.65
RXD: J_UART.5 R42.1 | length 7.2
  Top Layer w0.2: R42.1@13.35,48.65 v1(13.35,49.3)
  Bottom Layer w0.2: J_UART.5@13.07,55.69 13.07,49.58 v1(13.35,49.3)
SCK: J2.6 J2_DISP.6 R51.1 | length 4.5
  Top Layer w0.2: R51.1@11.8,48.65 J2_DISP.6@11.8,50.61 J2.6@11.8,53.15
SCK_RTS: R10.1 R43.2 R51.2 | length 70.6
  Top Layer w0.2: R43.2@10.85,47.55 R51.2@11.8,47.55 11.804,47.546 v1(12.46,47.546) ; v1(64.2,24.426) R10.1@64.2,24.9
  MidLayer2 w0.2: v1(12.46,47.546) 12.981,47.025 21.382,47.025 51.307,17.1 53.95,17.1 58.809,17.1 64.139,22.429 64.139,24.365 v1(64.2,24.426)
SCL: J2.10 J2_DISP.10 R23.1 U4.14 U5.17 U10.4 | length 70
  Top Layer w0.2: J2.10@1.64,53.15 J2_DISP.10@1.64,50.61 2.643,50.61 5.603,47.65 v1(6.3,47.65) R23.1@7.55,47.65 ; v1@4.55,37.375 v1(4.7,37.375) v1(5.9,37.375) 5.925,37.4 U5.17@7.81,37.4 ; v1(5.9,33.85) v1(5.9,34.9) ; v1(9.65,28.6) 9.95,28.6 10.5,29.15 U10.4@11.05,29.15 ; v1(34.175,39.275) 34.4,39.5 35.7,39.5 36.061,39.861 36.061,40.099 36.312,40.35 U4.14@36.711,40.35
  MidLayer2 w0.2: v1(4.7,37.375) 4.7,46.05 v1(6.3,47.65) ; v1(5.9,33.85) 5.9,30.5 7.8,28.6 v1(9.65,28.6) ; v1(5.9,34.9) v1(5.9,37.375) ; v1@6.008,34.892 27.822,34.892 v1(28.28,35.35)
  Bottom Layer w0.2: v1(28.28,35.35) 28.75,35.35 32.15,38.75 33.664,38.75 v1@34.175,39.261
SD_CS: J2.1 J2_DISP.1 | length 2.5
  Top Layer w0.2: J2_DISP.1@24.5,50.61 J2.1@24.5,53.15
SDA: J2.9 J2_DISP.9 R22.1 U4.15 U5.16 U10.6 | length 70.2
  Top Layer w0.2: J2.9@4.18,53.15 J2_DISP.9@4.18,50.61 6.165,48.625 v1(6.85,48.625) R22.1@7.55,48.625 ; v1(5.95,38.5) U5.16@7.81,38.5 ; v1(10.342,27.7) 11.6,27.7 11.9,28 U10.6@11.9,28.3 ; v1(34.825,38.9) 35.05,39.125 36.05,39.125 36.711,39.786 U4.15@36.711,39.95
  MidLayer2 w0.2: v1(5.95,38.5) 5.275,38.5 5.25,38.525 ; v1(6.85,48.625) 6.85,47.443 5.25,45.843 5.25,38.525 ; v1@10.35,27.7 10,28.05 7.65,28.05 5.25,30.45 5.25,34.4 ; v1(28.7,34.738) 28.362,34.4 5.25,34.4 ; 5.25,34.4 5.25,38.525
  Bottom Layer w0.2: v1(28.7,34.738) 32.312,38.35 34.27,38.35 v1@34.825,38.905
SX1280_NRESET: J4.1 R52.2 | length 62.5
  Top Layer w0.2: R52.2@61.8,34.8 61.8,35.2 v1(62,35.4)
  MidLayer1 w0.2: v1(50.7,13) v1(50.7,20.45)
  MidLayer2 w0.2: J4.1@33.5,4.89 34.89,3.5 41.3,3.5 42.45,4.65 42.45,5.094 50.356,13 v1(50.7,13) ; v1@50.7,20.457 47.45,23.707 47.45,34.15 50.85,37.55 60.782,37.55 62,36.332 v1(62,35.4)
SX9306_NRST: R12.1 R47.2 U4.17 | length 4.1
  Top Layer w0.2: R47.2@35.6,37.15 R12.1@35.6,38.05 35.6,38.45 35.8,38.65 37.525,38.65 37.761,38.886 U4.17@37.761,39.3
T_CS: J1.5 J1_DISP.5 | length 2.5
  Top Layer w0.2: J1_DISP.5@36.04,50.61 J1.5@36.04,53.15
T_IRQ: J1.3 J1_DISP.3 | length 2.5
  Top Layer w0.2: J1_DISP.3@41.12,50.61 J1.3@41.12,53.15
TFT_CS: J2.3 J2_DISP.3 | length 2.5
  Top Layer w0.2: J2_DISP.3@19.42,50.61 J2.3@19.42,53.15
TFT_D: J2.2 J2_DISP.2 | length 2.5
  Top Layer w0.2: J2_DISP.2@21.96,50.61 J2.2@21.96,53.15
TXD: J_UART.4 R4.1 | length 7.2
  Top Layer w0.2: R4.1@15.9,48.65 v1(15.9,49.3)
  Bottom Layer w0.2: J_UART.4@15.61,55.69 15.6,55.68 15.6,49.6 v1(15.9,49.3)
V_DCC: C6.2 C9.2 L4.1 U1.2 U1.12 | length 11.5
  Top Layer w0.35: U1.2@62.3,30.4 U1.2@62.3,30.65 62.3,31.35 v2(62.45,31.5)
  Top Layer w0.6: v2(62.45,31.5) C6.2@62.45,32
  Top Layer w0.65: L4.1@58.22,25.15 58.4,25.33 C9.2@58.4,27.15
  MidLayer2 w0.5: v2(58.98,27.156) 58.98,30.88 60,31.9 62.05,31.9 v2(62.45,31.5)
V_DCC2: L4.2 U1.14 | length 2.2
  Top Layer w0.35: L4.2@60.02,25.15 60.8,25.93 U1.14@60.8,26.85 U1.14@60.8,27.068
V_DIO: C8.2 R15.1 U1.11 | length 4.2
  Top Layer w0.4: C8.2@58.4,28.15 58.55,28.15 58.7,28 U1.11@59.65,28 U1.11@59.85,28
  Top Layer w0.5: 57.42,29.05 57.616,29.05 C8.2@58.355,28.311
  Top Layer w0.65: R15.1@56,29.05 57.42,29.05
V_PA: C5.2 U1.1 | length 1.8
  Top Layer w0.35: U1.1@62.8,30.4 U1.1@62.8,30.65 62.8,30.918 63.4,31.518 C5.2@63.4,32
VDD1V2_M: C32.2 C33.2 L12.2 R28.1 VDD1V2_M.1 | length 8.6
  Top Layer w0.8: L12.2@9.647,17.8 9.647,19.697 10.342,20.392 C32.2@10.342,21.594 R28.1@10.342,22.694 10.342,23.944 C33.2@10.392,23.994
  Top Layer w1: VDD1V2_M.1@8.342,23.994 C33.2@10.392,23.994
VDD3V3_M: C11.2 C12.2 C40.2 R1.2 R2.2 R26.1 U6.10 VDD_RADIO.1 | length 39.1
  Top Layer w0.2: U6.10@18.05,19.294 18.05,20.227 17.649,20.628 C11.2@17.649,22.017 17.965,22.334 C12.2@18.925,22.334
  Top Layer w0.9: R1.2@40.04,15.9 R1.2@40.04,15.99
  Top Layer w1: R1.2@40.04,15.99 40.05,16 VDD_RADIO.1@40.05,18.1 R2.2@40.05,20.3
  Top Layer w1.2: v2(37.7,19.75) v2(37.7,19) C40.2@37.7,18.1 VDD_RADIO.1@40.05,18.1
  MidLayer2 w1: v2(19.478,22.378) 21.428,22.378 26,26.95 36.05,26.95 37.7,25.3 v2(37.7,19.75)
VDD_3V3: C13.2 C20.1 C23.2 C41.2 C43.2 C45.2 C48.1 FB1.1 J_UART.3 R2.1 R11.1 R12.2 R13.2 R20.1 R21.2 R22.2 R23.2 R44.1 U3.5 U4.11 U5.7 U5.8 U9.5 U10.1 U10.14 | length 179.2
  Top Layer w0.25: C20.1@35.561,42.05 35.7,42.05 36.2,41.55 U4.11@36.711,41.55
  Top Layer w0.3: C43.2@9.85,30.65 U10.1@11.05,30.65 ; U10.14@12.9,31 C45.2@12.9,32.35
  Top Layer w0.4: v1(34.5,37.45) R12.2@34.5,38.05 ; v1(36.55,37.45) 36.561,37.461 R13.2@36.561,38.05 ; 42.025,26.9 44.275,29.15 49.557,29.15 51.634,31.227 C41.2@51.634,32.58 ; v1(51.634,33.25) C41.2@51.634,32.58 ; U9.5@52.669,32.58 C41.2@51.634,32.58 ; v1(55.65,35.1) 55.688,35.1 FB1.1@56.05,34.738
  Top Layer w0.5: C43.2@9.85,30.65 9.85,31.7 ; R44.1@10.35,26.95 9.7,26.95 7.4,29.25 7.4,31.15 7.95,31.7 9.85,31.7 ; C45.2@12.95,32.35 12.1,33.2 10.6,33.2 9.85,32.45 9.85,31.7
  Top Layer w0.6: v2(44.44,17.05) 44.44,20.3 ; v2(44.45,14.8) 64.95,14.8 69.839,19.689 C23.2@70.47,19.689 U3.5@71.343,19.689
  Top Layer w0.65: R23.2@8.65,47.65 10.05,46.25 18.862,46.25 v1(18.895,46.217) C48.1@18.895,44 ; U5.7@17.01,42.9 18.795,42.9 R20.1@18.895,43 C48.1@18.895,44 ; U5.8@17.01,44 C48.1@18.895,44 ; 32.6,38.139 32.689,38.05 R12.2@34.5,38.05 ; 32.6,40.15 32.625,40.125 R21.2@33.675,40.125 ; 32.6,41.075 32.625,41.1 R11.1@33.675,41.1 ; 35.45,43.2 35.561,43.089 C20.1@35.561,42.05
  Top Layer w0.7: C45.2@12.9,32.35 12.95,32.35 33.175,32.35 34.875,34.05
  Top Layer w1: v1(18.895,46.217) 20.082,46.217 23.099,43.2 32.625,43.2 ; 35.45,43.2 32.625,43.2 ; R2.1@41.871,20.35 43.09,20.35 44.44,20.35 ; 44.44,20.3 44.44,20.35 ; 32.625,43.2 32.6,43.175 32.6,41.075 32.6,40.15 32.6,38.139 32.6,36.325 34.875,34.05 42.025,26.9 44.44,24.485 44.44,20.35
  MidLayer2 w0.4: v1(34.5,37.45) v1(36.55,37.45) ; v1@51.65,33.25 53.5,35.1 v1(55.65,35.1)
  Bottom Layer w0.4: v1(51.634,33.25) v1@51.65,33.25
  Bottom Layer w0.6: J_UART.3@18.15,55.69 18.15,48.963 18.895,48.218 v1(18.895,46.217) ; v2(44.44,17.05) 44.44,14.81 v2(44.45,14.8)
VDD_RADIO: C7.2 C10.2 R1.1 R15.2 U1.15 VDD_RADIO.2 | length 36.9
  Top Layer w0.35: U1.15@61.3,27.097 U1.15@61.3,26.85 61.3,25.85 C10.2@61.4,25.75
  Top Layer w0.5: C10.2@61.4,25.75 C10.2@61.45,25.75
  Top Layer w0.65: v2(56,27.3) R15.2@56,27.95
  Top Layer w1: R1.1@41.593,15.9 43.09,15.9 54,15.9 57.05,18.95 v2(57.05,23.2) ; C7.2@42.59,15.95 VDD_RADIO.2@42.59,18.1
  MidLayer2 w0.65: v2(56,27.3) 56,24.25 v2(57.05,23.2) 61.525,23.2 62.175,23.85 62.175,25.15 61.925,25.4 61.925,25.425 v2(61.9,25.45)
  Bottom Layer w0.5: v2@61.85,25.498 61.852,25.498 v2(61.9,25.45)
VDISPLAY: C37.2 D1.2 D2.2 J3_DISP.5 | length 15
  Top Layer w1: J3_DISP.5@20.66,2.35 20.65,2.34 C37.2@20.65,1 v2(21.75,1) ; D1.2@23.75,9.55 D2.2@25.5,9.55 v2(25.5,8.3)
  MidLayer2 w0.3: v2(21.75,1) 22.044,1.294 22.044,2.894 22.75,3.6 23.9,3.6 24.69,4.39 24.69,5.325 25.5,6.135 v2(25.5,7.5) v2(25.5,8.3)
  other v2: 22.5,1
VLOAD: C27.2 C28.2 C29.2 C30.2 CHARGE.1 R38.1 R39.1 U6.11 U6.12 U6.18 U8.5 | length 54.9
  Top Layer w0.25: U6.12@17.4,18.244 16.906,18.244 16.506,18.644 U6.11@17.4,18.644 ; C27.2@18.65,14.644 C27.2@18.85,14.844 ; C27.2@18.85,15.194 U6.18@18.85,16.394 U6.18@18.85,16.675
  Top Layer w0.3: C28.2@18.65,13.044 C28.2@18.65,13.194
  Top Layer w0.4: U8.5@22.792,25.096 23.771,25.096 R39.1@23.867,25 C30.2@23.867,26.05 R38.1@25,26.05
  Top Layer w0.6: CHARGE.1@4.55,4.4 v1(4.55,5.05)
  Top Layer w0.8: C29.2@16.125,19.025 15.825,19.025 15.125,19.725 15.125,23.925 18.5,27.3 24.5,27.3 25.025,26.775 25.025,26.075 R38.1@25,26.05
  Top Layer w1: C28.2@18.65,13.194 C27.2@18.65,14.644
  MidLayer2 w0.4: v1(4.55,5.05) 4.55,5.375 5.825,6.65 14.4,6.65 18.65,10.9 18.65,13.044
  MidLayer2 w0.8: v2(15.15,20) 15.15,19.7 16.65,18.2 16.65,15.35 18.7,13.3 18.7,12.45
  other v2: 19,11.7 18.3,12.2 15.45,19.386
VMBED_IN: C38.2 D2.1 J3.8 R36.2 | length 10.8
  Top Layer w1.2: R36.2@26.45,14.544 28.7,12.294 D2.1@28.7,9.55 C38.2@28.7,7.1 28.7,5.425 28.28,5.005 J3.8@28.28,4.89
VUSB: C25.1 C26.2 C31.1 D1.1 J3.5 U6.1 U6.5 U6.7 U6.20 U8.2 | length 29.2
  Top Layer w0.2: U6.7@19.25,19.294 19.25,19.694 19.501,19.944 20.006,19.944 v1(20.3,19.65) U6.5@20.3,18.644 ; v2(20.1,24.448) v2@20.102,24.446 ; U6.1@20.3,17.044 v2(21.25,17.044)
  Top Layer w0.25: U6.20@19.65,16.394 19.65,15.644 C26.2@20.3,14.994
  Top Layer w0.4: v2@20.102,24.446 U8.2@20.892,24.446
  Top Layer w1.2: C25.1@20.3,13.294 C25.1@20.45,13.144 C25.1@20.55,13.044 ; C31.1@20.55,7.45 C31.1@20.65,7.35 C31.1@20.66,7.34
  Top Layer w1.3: C25.1@20.3,13.294 C26.2@20.3,14.994 ; C31.1@20.55,7.45 D1.1@20.55,9.55 C25.1@20.55,13.044 ; J3.5@20.66,4.89 C31.1@20.66,7.34
  MidLayer2 w0.4: v2(20.1,24.448) 20.046,24.448 18.45,22.852 18.45,22 19.15,21.3 20,21.3 21.25,20.05 21.25,19.65 ; v1(20.3,19.65) 21.25,19.65 ; v2(20.65,15.9) 21.25,16.5 v2(21.25,17.044) 21.25,19.65
  MidLayer2 w0.8: v2(19.95,15.9) v2(20.65,15.9)
XTA: C47.2 Q1.3 U1.4 | length 4.5
  Top Layer w0.2: C47.2@60.575,34.75 Q1.3@60.575,32.875 60.679,32.875 61.3,32.254 U1.4@61.3,30.65
pads on no net: J1.1 J1.2 J1_DISP.1 J1_DISP.2 J1_DISP.4 J1_DISP.6 J1_DISP.8 J2.8 J2_DISP.8 J3.1 J3.2 J3.4 J3_DISP.1 J3_DISP.2 J3_DISP.4 J3_DISP.8 J4_DISP.1 J4_DISP.2 J4_DISP.3 J4_DISP.4 J4_DISP.5 J4_DISP.6 U3.1 U4.1 U4.4 U4.5 U4.7 U4.8 U4.9 U4.10 U5.2 U5.3 U5.5 U5.9 U5.13 U5.15 U5.18 U6.3 U8.1 U10.3 U10.8 U10.13 U10.15 U10.16

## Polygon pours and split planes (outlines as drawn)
GND on MidLayer1 "GND midlayer1" (solid, pour order 11): 56,0.5 66.15,0.5 94.43,28.78 94.43,29.23 66.21,57.5 56,57.5
GND on MidLayer1 "GND Bottom" (solid, remove dead copper, pour order 13): 0.35,0.5 56.4,0.5 56.4,57.5 0.35,57.5
VDISPLAY on MidLayer2 "VDISPLAY" (solid, pour order 14): 21.3,0.5 25.55,0.5 26.95,1.9 26.95,5.4 26,6.35 26,8.75 24.6,8.75 24.6,6.225 24.35,5.975 22.55,5.975 21.65,5.075 21.65,1.9 21.3,1.55
GND on Top Layer "GND Top RF" (solid, remove dead copper, pour order 8): 65,2.75 68.4,2.75 94.43,28.78 94.43,29.23 68.41,55.25 65,55.25
GND on Top Layer "GND Top" (solid, remove dead copper, pour order 9): 0.35,2.75 68,2.75 68,55.25 0.35,55.25
GND on Bottom Layer "Bot GND" (solid, remove dead copper, pour order 10): 64.5,2.75 68.4,2.75 94.43,28.78 94.43,29.23 68.41,55.25 64.5,55.25
GND on Bottom Layer "GND Bottom" (solid, remove dead copper, pour order 12): 0.35,2.75 67,2.75 67,55.25 0.35,55.25

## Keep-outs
Keep-Out Layer:
  the board outline again, w0.05

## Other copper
Top Layer:
  region net GND: 72.65,31.219 73.8,31.219 73.8,31.65 72.65,31.65
  region net GND: 72.6,26.8 73.875,26.8 73.875,26.35 72.6,26.35
  region net GND: 64,27.85 64,27.25 64.45,27.25 64.45,27.85
  region net GND: 71.15,28.425 63.747,28.425 63.747,27.831 63.999,27.659 71.15,27.659
  region net GND: 77.836,30.573 81.005,33.742 81.399,33.349 78.233,30.183
  region net GND: 77.556,27.707 81.115,24.148 81.499,24.532 77.941,28.091
  region net GND: 9.1,29.1 9.1,31.296 8.114,31.296 8.114,30.65 8.55,30.65 8.55,29.1
  pour cut-out: 13.45,28.95 11.836,28.95 11.636,28.75 13.5,28.75
  pour cut-out: 11.5,28.9 11.5,28.901 11.65,29.051 11.647,29.054 11.647,30.4 13.532,30.4 13.55,30.382 13.55,30.487 11.568,30.487 11.538,30.457 11.538,29.1
  region net GND: 57,35.038 59.95,35.038 59.95,34.35 57,34.35
  pour cut-out: 60.601,30.839 60.601,31.097 60.498,31.2 60.477,31.2 60.477,31.102 60.475,31.1 60.55,31.025 60.55,30.947
  pour cut-out: 60.999,30.839 60.999,31.496 61.003,31.5 61.053,31.45 61.057,31.45 61.057,30.86
  region net GND: 60.669,27.425 62.824,27.425 62.899,27.5 62.899,28.635 62.77,28.765 62.77,29.705 62.4,30.074 60.201,30.074 60.201,27.5
  pour cut-out: 62.981,27.379 62.892,27.425 60.7,27.425 60.602,27.327 60.652,27.294 62.972,27.294 62.981,27.3
  pour cut-out: 62.8,30.074 61.205,30.074 61.123,30.157 61.168,30.202 62.93,30.202 62.932,30.2
  pour cut-out: 60.393,30.114 60.298,30.074 60.201,30.074 60.201,27.5 60.173,27.5 60.13,27.543 60.13,30.157
  region net V_DCC: 58.075,27.516 59.056,27.516 59.19,27.65 59.957,27.65 60.051,27.556 60.051,27.431 59.897,27.277 59.557,27.277 59.11,26.83 58.075,26.83
  region net GND: 43.989,12.85 43.989,14.82 43.94,14.869 43.576,14.869 43.576,12.85
  region net V_DIO: 57.958,29.06 57.643,29.375 57.245,29.375 57.245,28.725 57.587,28.725 57.696,28.616 58.05,28.97
  region net GND: 62.401,24.038 62.401,25 61.137,25 60.951,24.815 60.951,24.038
  region net GND: 62.05,33.75 62.05,33.25 62.051,32.649 62.2,32.5 63.973,32.5 64.049,32.576 64.049,33.294 62.45,33.294 62.45,33.75
  region net V_DCC2: 60.97,26.44 60.97,25.6 60.96,25.59 60.57,25.2 60.241,25.2 59.999,25.442 59.999,25.75 60.13,25.75 60.82,26.44
  region net GND: 59.8,31.45 60.3,31.45 60.3,31.7 59.8,31.7
  pour cut-out: 58.927,24.2 59.293,24.2 59.293,24.3 58.927,24.3
  pour cut-out: 58.837,26.1 59.323,26.1 59.323,26.056 58.862,26.056
  region net VDD_RADIO: 62.25,25.15 62.25,25.599 61.125,26.729 61.125,25.15
  region net V_DCC: 62.124,30.967 62.124,31.819 62.145,31.84 62.774,31.84 62.774,31.4 62.452,31.078 62.452,30.964
  region net VUSB: 19.525,16.675 19.525,15.275 20.8,14 20.95,14 20.95,16.2 20.149,16.2 19.649,16.7 19.55,16.7
  region net NetC35_2: 25.925,19.125 25.8,19 25.8,17.95 26.775,17.95 26.125,18.6 26.125,19 26,19.125
  region net VDISPLAY: 26,8.75 26,7.15 25,7.15 25,8.8 25.05,8.85 25.95,8.85
  region net VDISPLAY: 21.35,1.5 22.8,1.5 22.9,1.4 22.9,0.608 22.792,0.5 21.35,0.5
  region net VLOAD: 18.9,16.75 18.95,16.7 18.95,16 19.3,15.65 19.3,14.9 18.075,14.9 18.075,14.975 18.749,15.649 18.749,16.699 18.8,16.75
  region net NetL12_1: 15.673,17.423 16.1,17.85 15.7,18.25 14.725,18.25 14.012,18.962 13.925,18.875 13.925,16.875 14.125,16.875 14.673,17.423
  region net VLOAD: 17.7,18.592 17.655,18.547 16.65,18.547 16.347,18.85 16.2,18.85 16.2,19.475 16.325,19.475 17.05,18.75 17.625,18.75 17.7,18.675
  region net VLOAD: 16.925,18.369 16.775,18.369 16.775,18.55 16.925,18.55
  region net VDD3V3_M: 18.18,21.08 18.3,21.2 18.3,21.467 18.783,21.95 20.55,21.95 20.55,22.807 17,22.807 17,20.5 17.9,19.6 17.9,19.45 17.964,19.386 18.1,19.386 18.18,19.45
  region net NetC34_2: 26.2,21.75 26.2,22.184 26.6,22.584 26.6,22.694 26.156,22.694 26.05,22.7 26.05,21.85
  region net NetC35_2: 24.8,15.3 24.8,16.025 24.825,16.05 27.094,16.05 27.1,16.044 27.1,15.4 25.65,15.4 25.55,15.3
  region net NetL13_1: 26.5,22.05 29.3,22.05 29.667,22.417 29.667,21.083 29.3,21.45 26.5,21.45
  region net NetL13_2: 26.5,19.15 29.3,19.15 29.55,19.4 29.75,19.4 29.75,18.083 29.283,18.55 26.5,18.55
  region net GND: 27.6,22.55 27.6,26.35 36.25,26.35 36.8,25.8 36.8,14.898 36.202,14.3 28.1,14.3 27.5,14.9 27.5,18.15 28.9,18.15 28.9,17.15 29.1,16.95 35.3,16.95 35.5,17.15 35.5,23.362 35.212,23.65 28.9,23.65 28.9,22.55
  region net GND: 5.4,10.55 5.4,8.75 10.7,8.75 10.7,10.55
  region net GND: 12.1,22.36 12.1,23.1 11.9,23.3 11.5,23.3 11.5,24.65 13.65,24.65 13.7,24.6 13.7,22.36
  region net GND: 17.5,11.6 16.95,11.05 11.8,11.05 11.8,12.23 12.621,13.044 15.827,13.044 16.2,13.416 16.2,15.275 17.5,15.275
  region net GND: 19.9,0.5 19.9,1.5 19.55,1.85 19.2,1.85 18.6,1.25 18.6,0.5
  region net GND: 24.25,8.25 22,8.25 22,6.45 24.25,6.45
  region net GND: 26.2,6.45 26.2,8.4 27.65,8.4 27.65,6.45
  region net VLOAD: 18,14.25 18,11.35 19.3,11.35 19.3,14.25
  region net GND: 17,23.15 17,24.85 17.336,25.186 19.45,25.186 19.45,23.102 17.048,23.102
  region net GND: 15.675,20.85 15.675,22.8 16.575,22.8 16.575,20.85
  region net GND: 24.375,16.275 24.375,18 23.075,18 23.075,16.475 23.275,16.275
  region net GND: 24.7,18.95 24.7,19.65 24.325,19.65 24.3,19.625 24.3,18.95
  region net GND: 21.45,16.25 21.45,14.35 21.875,14.35 21.875,11.45 24.775,11.45 24.775,14.085 23.59,14.085 23.35,14.325 23.35,15.117 22.75,15.717 22.75,16.25
  region net GND: 24.825,15.075 25.65,15.075 25.65,14.275 25.775,14.15 25.775,13.75 24.909,13.75 24.909,14.166 24.825,14.25 24.825,14.275
  region net NetBAT1_1: 5.4,12.65 5.4,10.7 10.7,10.7 10.7,12.65
  region net GND: 0.35,1.5 2.5,1.5 2.5,4.6 4.9,7 4.95,7 4.95,13.569 8.169,13.569 8.35,13.75 8.35,20.55 8.6,20.8 9.497,20.8 9.65,20.953 9.65,22.55 9.45,22.75 7.85,22.75 7.05,23.55 7.05,24.45 7.8,25.2 15.052,25.2 16.202,26.35 0.35,26.35
  region net GND: 37.05,14.911 37.05,17.274 37.064,17.26 37.283,17.26 37.283,14.892
  pour cut-out: 6.5,43.3 6.5,44.7 9.1,44.7 9.1,43.3
  pour cut-out: 6.473,40.4 6.473,35.711 9.139,35.711 9.15,35.7 9.15,42.5 9.009,42.5 9.016,42.493 9.016,35.875 6.6,35.875 6.6,40.344
  pour cut-out: 18.347,41.45 18.347,36.703 18.35,36.7 15.65,36.7 15.65,45.7 15.7,45.65 18.347,45.65 18.347,44.697 18.3,44.65 18.244,44.65 18.244,45.482 18.286,45.525 15.8,45.525 15.8,36.823 15.827,36.85 18.152,36.85 18.152,36.958 18.267,37.074 18.267,41.45
  region net GND: 16.85,36.35 16.85,35.45 16.9,35.4 17.45,35.4 17.45,36.35
  pour cut-out: 2.5,1.3 2.5,4.6 2.525,4.6 4.95,7.025 4.95,13.5 8.274,13.5 8.35,13.576 8.35,20.55 8.6,20.8 9.497,20.8 9.65,20.953 9.65,22.55 9.45,22.75 7.85,22.75 7.85,22.8 7.05,23.6 7.05,24.49 7.81,25.25 15.132,25.25 18.032,28.15 25.15,28.15 26.35,26.95 36.632,26.95 37.05,26.532 37.05,14.569 36.381,13.9 30.217,13.9 29.6,13.283 29.6,2.35 27.65,0.4 18.387,0.4 18.237,0.55 18.237,2.15 18.95,2.15 19.537,2.738 19.537,10.012 18.95,10.6 11.65,10.6 11.125,10.075 11.125,8.725 10.8,8.4 5.5,8.4 5.5,1.3
  region net VDD_3V3: 8.325,48.95 8.325,47.325 8.975,47.325 8.975,48.95
  region net GND: 50.9,31.831 50.9,33.15 50.6,33.15 50.5,33.05 50.5,31.831
  pour cut-out: 63.107,28.35 63.107,28.15 63.65,28.15 63.65,28.35
  pour cut-out: 63.153,29.85 63.153,29.65 63.65,29.65 63.65,29.85
  region net NetANT0_1: 85.607,38.45 85.03,38.45 84.9,38.58 84.9,39.157 85.002,39.259 85.709,38.552
  region net NetANT1_1: 84.9,18.843 84.9,19.47 84.98,19.55 85.607,19.55 85.766,19.391 85.059,18.684
  region net GND: 56.65,28.574 57.501,28.574 57.924,28.151 57.924,26.35 57.325,26.35 57.3,26.325 57.3,28.15 56.65,28.15
  region net GND: 73.55,28.05 73.75,28.05 73.75,28.7 73.95,28.9 73.95,29.1 73.75,29.3 73.75,30 73.55,30
  region net GND: 63.875,28.55 63.775,28.65 62.775,28.65 62.775,28.35 63.85,28.35 63.875,28.325
  region net GND: 63.775,29.35 63.875,29.45 63.875,29.65 62.8,29.65 62.8,29.35
MidLayer1:
  region net GND: 18.25,17.217 19.486,17.217 19.5,17.203 19.5,18.494 18.256,18.494 18.25,18.5
MidLayer2:
  region net VDD3V3_M: 37.2,20.05 37.2,18.768 37.318,18.65 38.05,18.65 38.2,18.8 38.2,20.05
  region net VLOAD: 18,11.35 18,12.65 19.3,12.65 19.3,11.35
  region net VLOAD: 14.75,20.4 15.45,20.4 15.55,20.3 15.55,19.85 15.85,19.55 15.85,19.05 15.55,18.75 14.75,19.55
Bottom Layer:
  region net GND: 37.39,41.55 37.39,39.95 38.95,39.95 38.95,41.55
  region net GND: 18.273,18.433 18.273,17.27 19.451,17.27 19.451,18.433
  region net NetBAT1_1: 9.321,12.6 9.321,10.8 10.7,10.8 10.7,12.6

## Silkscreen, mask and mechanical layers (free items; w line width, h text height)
Top Overlay:
  lines w0.15: 60.1,33.65 56.774,33.65 56.774,24.05 72.7,24.05 72.7,27.649 ; 66.3,0.3 84.7,18.7 ; 66.3,57.7 84.7,39.3 ; 72.7,30.2 72.7,33.65 61.057,33.65 ; 61.057,33.65 61.057,33.65
  text "1" at 25.117,55.121 h1
  text "1" at 47.511,52.71 h1
  text "1" at 26,52.61 h1
  text "J2" at 23.2,47.6 h1.27
  text "J1" at 45.621,47.6 h1.27
  text "SX1280 Evaluation Board" at 48.786,43.36 h1.1
  text "Reference" at 63.2,36.238 h1.1
  text "Design" at 66.499,34.388 h1.1
  text "SX1280" at 65.55,24.55 h1.2
  text "PCB_E394V02A 0117" at 53.556,12.4 h1
  text "J3" at 9.45,6.85 h1.27
  text "J4" at 32.4,6.85 h1.27
  text "1" at 8.911,4.41 h1
  text "1" at 31.731,4.415 h1
Bottom Overlay:
  text "RoHS" at 25.144,26.82 h2.2 r270
  text "compliant" at 23.594,24.77 h2.2 r270
  text "PCB_E394V02A 0117" at 46.75,20.95 h1 r270
Mechanical 3:
  text "Origin(0;0)" at -10,-1.55 h1
Mechanical 14:
  the board outline again, w0.05
Mechanical 15:
  lines w0.05: -1,29 110,29
  lines w0.3: 65.6,0 93.05,27.45 93.05,30.45 ; 65.6,58 93.15,30.45

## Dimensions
0,0 to 6.4,11.6 on Mechanical 3
0,0 to 6.4,11.6 on Mechanical 3
0,0 to 0,58 on Mechanical 3
0,0 to 104.5,0 on Mechanical 3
